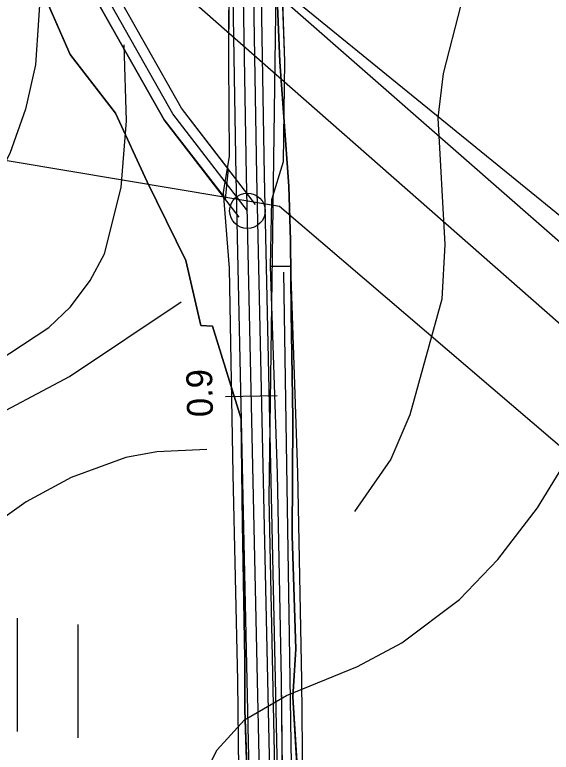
# Model space of a CAD drawing. Extents: x -662620 to -656370, y -1067090 to -1062990.
# Drawn here: x -660531.2 to -660427.3, y -1064236 to -1064093.3 of the extents above; entities that cross this region are included whole.
import ezdxf

# ---------------------------------------------------------------- set-up
doc = ezdxf.new("R2010")
doc.units = 0
for name, color, linetype in [('CESTA_ZABOR', 7, 'Continuous'), ('Default', 7, 'Continuous'), ('ELEK__VEDENÍ_VN_-_NADZEMNÍ', 7, 'Continuous'), ('ELEK__VEDENÍ_VVN_-_NADZEMNÍ', 7, 'Continuous'), ('Krajinná_zeleň_-_liniová_-_návrh', 7, 'Continuous'), ('Ochr__pás__vod__zdroje_II__stupně', 7, 'Continuous'), ('Odvodnení_cesty_príkopem_-_navržené', 7, 'Continuous'), ('ORNÁ_PŮDA_-_STÁVAJÍCÍ', 7, 'Continuous'), ('ORNÁ_PŮDA_-_ZNAČKA', 7, 'Continuous'), ('OSTATNÍ_PLOCHA_-_NAVRŽENÁ', 7, 'Continuous'), ('OSTATNÍ_PLOCHA_-_STÁVAJÍCÍ', 7, 'Continuous'), ('POLNÍ_CESTA_NAVRŽENÁ_-_OSA', 7, 'Continuous'), ('POLNÍ_CESTA_STÁVAJÍCÍ_-_KRAJ', 7, 'Continuous'), ('POLNÍ_CESTA_STÁVAJÍCÍ_-_OSA', 7, 'Continuous'), ('Trvalý_trávní_porost_-_stávající', 7, 'Continuous'), ('VRSTEVNICE_ZDŮRAZNĚNÁ', 7, 'Continuous'), ('VRSTEVNICE_ZÁKLADNÍ', 7, 'Continuous')]:
    doc.layers.add(name, color=color, linetype=linetype)

msp = doc.modelspace()

# ---------------------------------------------------------------- linework, layer by layer
at = {"layer": 'CESTA_ZABOR'}
for p, q in [((-660489.74, -1064102.3), (-660489.62, -1064062.36)), ((-660480.31, -1064062.11), (-660478.98, -1064102.23)), ((-660489.61, -1064120.63), (-660489.74, -1064102.3)), ((-660478.98, -1064102.23), (-660479.21, -1064121.73)), ((-660490.79, -1064127.68), (-660489.61, -1064120.63)), ((-660479.21, -1064121.73), (-660481.5, -1064129.07)), ((-660489.62, -1064142.29), (-660490.79, -1064127.68)), ((-660481.5, -1064129.07), (-660481.76, -1064141.99)), ((-660481.76, -1064141.99), (-660480.35, -1064182.06)), ((-660488.92, -1064182.19), (-660489.62, -1064142.29)), ((-660487.99, -1064222.18), (-660488.92, -1064182.19)), ((-660480.35, -1064182.06), (-660479.6, -1064222.07)), ((-660487.56, -1064262.16), (-660487.99, -1064222.18)), ((-660479.6, -1064222.07), (-660479.22, -1064262.06))]:
    msp.add_line(p, q, dxfattribs=at)
for points in [[(-660476.62, -1064381.82), (-660481.51, -1064342.23), (-660485.81, -1064302.25), (-660487.55, -1064267.89), (-660487.56, -1064262.16), (-660487.99, -1064222.18), (-660488.92, -1064182.19), (-660489.62, -1064142.29), (-660490.79, -1064127.68), (-660489.61, -1064120.63), (-660489.74, -1064102.3), (-660489.62, -1064062.36), (-660491.41, -1064022.4), (-660491.82, -1063995.6), (-660491.58, -1063993.71), (-660486.92, -1063981.87), (-660480, -1063962.07), (-660476.39, -1063948.94), (-660467.64, -1063925.93), (-660459.11, -1063911.53), (-660457.57, -1063907.35), (-660441.43, -1063870.67), (-660426.53, -1063833.6), (-660410.61, -1063796.9)], [(-660402.21, -1063800.45), (-660418.38, -1063837.05), (-660433.34, -1063874.17), (-660449.71, -1063910.53), (-660464.44, -1063947.85), (-660478.91, -1063984.7), (-660482.04, -1063997.01), (-660482.49, -1064022.32), (-660480.31, -1064062.11), (-660478.98, -1064102.23), (-660479.21, -1064121.73), (-660481.5, -1064129.07), (-660481.76, -1064141.99), (-660480.35, -1064182.06), (-660479.6, -1064222.07), (-660479.22, -1064262.06), (-660478.9, -1064274.43), (-660477.62, -1064301.81), (-660473.42, -1064341.28), (-660468.75, -1064381.18)], [(-660588.24, -1064193.5), (-660573.01, -1064125.57), (-660556.63, -1064051.98), (-660554.66, -1064044.43), (-660549.46, -1064039.91), (-660543.17, -1064040.28), (-660539.05, -1064046.15), (-660522.38, -1064077.97), (-660502.25, -1064113.58), (-660490.41, -1064128.91), (-660489.78, -1064123.16), (-660498.9, -1064111.37), (-660518.86, -1064076.05), (-660535.63, -1064044.06), (-660541, -1064036.4), (-660550.85, -1064035.83), (-660558.22, -1064042.22), (-660560.52, -1064051.04), (-660576.91, -1064124.7), (-660592.14, -1064192.62), (-660588.24, -1064193.5), (-660588.24, -1064193.5)], [(-660588.24, -1064193.5), (-660573.01, -1064125.57), (-660556.63, -1064051.98), (-660554.66, -1064044.43), (-660549.46, -1064039.91), (-660543.17, -1064040.28), (-660539.05, -1064046.15), (-660522.38, -1064077.97), (-660502.25, -1064113.58), (-660490.41, -1064128.91), (-660489.78, -1064123.16), (-660498.9, -1064111.37), (-660518.86, -1064076.05), (-660535.63, -1064044.06), (-660541, -1064036.4), (-660550.85, -1064035.83), (-660558.22, -1064042.22), (-660560.52, -1064051.04), (-660576.91, -1064124.7), (-660592.14, -1064192.62)]]:
    msp.add_lwpolyline(points, dxfattribs=at)
at = {"layer": 'ELEK__VEDENÍ_VN_-_NADZEMNÍ'}
msp.add_lwpolyline([(-661430.18, -1063973.15), (-661341.18, -1063987.78), (-661252.56, -1064002.41), (-661162.74, -1064017.32), (-661072.57, -1064032.36), (-660982.83, -1064047.06), (-660895.64, -1064061.52), (-660803.93, -1064076.92), (-660722.98, -1064090.23), (-660635.7, -1064104.5), (-660551.96, -1064118.27), (-660479.9, -1064130.34), (-660406.54, -1064193.02), (-660334.59, -1064253.68), (-660260.25, -1064316.77)], dxfattribs=at)
at = {"layer": 'ELEK__VEDENÍ_VVN_-_NADZEMNÍ'}
for points in [[(-659212.59, -1064402.76), (-659241.86, -1064399.78), (-659588.53, -1064364.37), (-659927.91, -1064329.98), (-660254.66, -1064303.24), (-660516.66, -1064073.17), (-660833.72, -1063804.76), (-661111.8, -1063569.65)], [(-660509.03, -1064064.22), (-660244.71, -1064279.23)], [(-659926.77, -1064317.9), (-660249.79, -1064291.25), (-660509.03, -1064064.22)], [(-660509.03, -1064064.22), (-660244.71, -1064279.23), (-659926.77, -1064317.9)], [(-660254.66, -1064303.24), (-660516.66, -1064073.17)]]:
    msp.add_lwpolyline(points, dxfattribs=at)
at = {"layer": 'Krajinná_zeleň_-_liniová_-_návrh'}
msp.add_lwpolyline([(-660463.41, -1064442), (-660476.87, -1064283.86), (-660479.09, -1064143.11)], dxfattribs=at)
at = {"layer": 'Ochr__pás__vod__zdroje_II__stupně'}
msp.add_lwpolyline([(-660464.98, -1064477.66), (-660479.16, -1064319.24), (-660481.94, -1064186.81), (-660479.3, -1063994.59), (-660360.21, -1063702.35), (-660281.08, -1063700.79), (-660243.47, -1063702.35), (-660222.31, -1063711.76), (-660211.34, -1063724.29), (-660187.06, -1063774.43), (-660164.34, -1063811.26), (-660075.02, -1063846.52), (-660042.89, -1063862.97), (-660047.59, -1063878.64), (-659927.67, -1063941.34), (-659907.68, -1063958.21), (-659897.75, -1063968.57), (-659822.34, -1063992.17), (-659732.05, -1064020.39)], dxfattribs=at)
at = {"layer": 'Odvodnení_cesty_príkopem_-_navržené'}
msp.add_lwpolyline([(-660558.09, -1065055.87), (-660475.04, -1064666.65), (-660471.14, -1064652.96), (-660465.99, -1064629.97), (-660464, -1064613.86), (-660457.68, -1064584.26), (-660456.26, -1064575.18), (-660454.42, -1064557.77), (-660456.24, -1064538.9), (-660463.06, -1064471.1), (-660479.37, -1064283.99), (-660482.8, -1064124.36), (-660484.72, -1064013.14), (-660484.26, -1063999.81), (-660482.47, -1063990.24), (-660478.65, -1063978.94), (-660368.35, -1063708.74)], dxfattribs=at)
at = {"layer": 'ORNÁ_PŮDA_-_STÁVAJÍCÍ'}
for p, q in [((-660479.89, -1064102.35), (-660481.05, -1064074.37)), ((-660478.1, -1064126.45), (-660479.89, -1064102.35)), ((-660477.81, -1064136.93), (-660478.1, -1064126.45)), ((-660477.69, -1064150.75), (-660477.81, -1064136.93)), ((-660477.33, -1064171.48), (-660477.69, -1064150.75)), ((-660477.47, -1064194.07), (-660477.33, -1064171.48)), ((-660476.74, -1064216.04), (-660477.47, -1064194.07)), ((-660477.34, -1064225.29), (-660476.74, -1064216.04)), ((-660476.34, -1064241.78), (-660477.34, -1064225.29))]:
    msp.add_line(p, q, dxfattribs=at)
msp.add_lwpolyline([(-660470.29, -1064374.22), (-660471.09, -1064362.63), (-660471.94, -1064349.57), (-660473.08, -1064336.89), (-660473.74, -1064320.03), (-660474.29, -1064302.76), (-660474.79, -1064291.24), (-660476.03, -1064274.2), (-660476.13, -1064259.82), (-660476.34, -1064241.78), (-660477.34, -1064225.29), (-660476.74, -1064216.04), (-660477.47, -1064194.07), (-660477.33, -1064171.48), (-660477.69, -1064150.75), (-660477.81, -1064136.93), (-660478.1, -1064126.45), (-660479.89, -1064102.35), (-660481.05, -1064074.37)], dxfattribs=at)
at = {"layer": 'ORNÁ_PŮDA_-_ZNAČKA'}
for points in [[(-660530.7, -1064210.08), (-660530.7, -1064232.01)], [(-660519, -1064211.31), (-660519, -1064233.24)]]:
    msp.add_lwpolyline(points, dxfattribs=at)
at = {"layer": 'OSTATNÍ_PLOCHA_-_NAVRŽENÁ'}
msp.add_lwpolyline([(-660481.76, -1064141.99), (-660480.35, -1064182.06), (-660479.6, -1064222.07), (-660479.22, -1064262.06), (-660478.9, -1064274.43), (-660477.62, -1064301.81), (-660473.42, -1064341.28), (-660468.75, -1064381.18), (-660465.77, -1064421.09), (-660463.02, -1064443.82), (-660461.97, -1064448.3), (-660459.31, -1064450.58), (-660461.78, -1064420.77), (-660464.77, -1064380.8), (-660469.45, -1064340.83), (-660473.63, -1064301.5), (-660474.9, -1064274.29), (-660475.22, -1064261.99), (-660475.6, -1064222.01), (-660476.35, -1064181.95), (-660477.76, -1064141.96)], close=True, dxfattribs=at)
msp.add_lwpolyline([(-660481.76, -1064141.99), (-660480.35, -1064182.06), (-660479.6, -1064222.07), (-660479.22, -1064262.06), (-660478.9, -1064274.43), (-660477.62, -1064301.81), (-660473.42, -1064341.28), (-660468.75, -1064381.18), (-660465.77, -1064421.09), (-660463.02, -1064443.82), (-660461.97, -1064448.3), (-660459.31, -1064450.58), (-660461.78, -1064420.77), (-660464.77, -1064380.8), (-660469.45, -1064340.83), (-660473.63, -1064301.5), (-660474.9, -1064274.29), (-660475.22, -1064261.99), (-660475.6, -1064222.01), (-660476.35, -1064181.95), (-660477.76, -1064141.96)], close=True, dxfattribs=at)
at = {"layer": 'OSTATNÍ_PLOCHA_-_STÁVAJÍCÍ'}
for p, q in [((-660481.05, -1064074.37), (-660479.89, -1064102.35)), ((-660481.05, -1064074.37), (-660479.89, -1064102.35)), ((-660520.43, -1064100.97), (-660529.29, -1064080.76)), ((-660520.43, -1064100.97), (-660529.29, -1064080.76)), ((-660511.66, -1064112.29), (-660520.43, -1064100.97)), ((-660511.66, -1064112.29), (-660520.43, -1064100.97)), ((-660479.89, -1064102.35), (-660478.1, -1064126.45)), ((-660479.89, -1064102.35), (-660478.1, -1064126.45)), ((-660505.56, -1064125.57), (-660511.66, -1064112.29)), ((-660505.56, -1064125.57), (-660511.66, -1064112.29)), ((-660498.07, -1064140.85), (-660505.56, -1064125.57)), ((-660498.07, -1064140.85), (-660505.56, -1064125.57)), ((-660478.1, -1064126.45), (-660477.81, -1064136.93)), ((-660478.1, -1064126.45), (-660477.81, -1064136.93)), ((-660477.81, -1064136.93), (-660477.69, -1064150.75)), ((-660477.81, -1064136.93), (-660477.69, -1064150.75)), ((-660495.19, -1064153.41), (-660498.07, -1064140.85)), ((-660495.19, -1064153.41), (-660498.07, -1064140.85)), ((-660477.69, -1064150.75), (-660477.33, -1064171.48)), ((-660477.69, -1064150.75), (-660477.33, -1064171.48)), ((-660492.89, -1064153.57), (-660495.19, -1064153.41)), ((-660492.89, -1064153.57), (-660495.19, -1064153.41)), ((-660487.32, -1064171.49), (-660492.89, -1064153.57)), ((-660487.32, -1064171.49), (-660492.89, -1064153.57)), ((-660487.12, -1064191.78), (-660487.32, -1064171.49)), ((-660487.12, -1064191.78), (-660487.32, -1064171.49)), ((-660477.33, -1064171.48), (-660477.47, -1064194.07)), ((-660477.33, -1064171.48), (-660477.47, -1064194.07)), ((-660486.64, -1064217.91), (-660487.12, -1064191.78)), ((-660486.64, -1064217.91), (-660487.12, -1064191.78)), ((-660477.47, -1064194.07), (-660476.74, -1064216.04)), ((-660477.47, -1064194.07), (-660476.74, -1064216.04)), ((-660476.74, -1064216.04), (-660477.34, -1064225.29)), ((-660476.74, -1064216.04), (-660477.34, -1064225.29)), ((-660486.67, -1064227.81), (-660486.64, -1064217.91)), ((-660486.67, -1064227.81), (-660486.64, -1064217.91)), ((-660477.34, -1064225.29), (-660476.34, -1064241.78)), ((-660477.34, -1064225.29), (-660476.34, -1064241.78)), ((-660486.09, -1064244.12), (-660486.67, -1064227.81)), ((-660486.09, -1064244.12), (-660486.67, -1064227.81))]:
    msp.add_line(p, q, dxfattribs=at)
for points in [[(-660479.03, -1064374.35), (-660481.22, -1064361.46), (-660482.83, -1064343.31), (-660485.34, -1064319.01), (-660524.58, -1064322.57), (-660499.48, -1064320.24), (-660485.42, -1064318.9), (-660485.23, -1064289.19), (-660485.99, -1064273.97), (-660486.31, -1064260.54), (-660486.09, -1064244.12), (-660486.67, -1064227.81), (-660486.64, -1064217.91), (-660487.12, -1064191.78), (-660487.32, -1064171.49), (-660492.89, -1064153.57), (-660495.19, -1064153.41), (-660498.07, -1064140.85), (-660505.56, -1064125.57), (-660511.66, -1064112.29), (-660520.43, -1064100.97), (-660529.29, -1064080.76), (-660534.95, -1064065.62)], [(-660479.03, -1064374.35), (-660481.22, -1064361.46), (-660482.83, -1064343.31), (-660485.34, -1064319.01), (-660524.58, -1064322.57), (-660499.48, -1064320.24), (-660485.42, -1064318.9), (-660485.23, -1064289.19), (-660485.99, -1064273.97), (-660486.31, -1064260.54), (-660486.09, -1064244.12), (-660486.67, -1064227.81), (-660486.64, -1064217.91), (-660487.12, -1064191.78), (-660487.32, -1064171.49), (-660492.89, -1064153.57), (-660495.19, -1064153.41), (-660498.07, -1064140.85), (-660505.56, -1064125.57), (-660511.66, -1064112.29), (-660520.43, -1064100.97), (-660529.29, -1064080.76), (-660534.95, -1064065.62)], [(-660481.05, -1064074.37), (-660479.89, -1064102.35), (-660478.1, -1064126.45), (-660477.81, -1064136.93), (-660477.69, -1064150.75), (-660477.33, -1064171.48), (-660477.47, -1064194.07), (-660476.74, -1064216.04), (-660477.34, -1064225.29), (-660476.34, -1064241.78), (-660476.13, -1064259.82), (-660476.03, -1064274.2), (-660474.79, -1064291.24), (-660474.29, -1064302.76), (-660473.74, -1064320.03), (-660473.08, -1064336.89), (-660471.94, -1064349.57), (-660471.09, -1064362.63), (-660470.29, -1064374.22)], [(-660481.05, -1064074.37), (-660479.89, -1064102.35), (-660478.1, -1064126.45), (-660477.81, -1064136.93), (-660477.69, -1064150.75), (-660477.33, -1064171.48), (-660477.47, -1064194.07), (-660476.74, -1064216.04), (-660477.34, -1064225.29), (-660476.34, -1064241.78), (-660476.13, -1064259.82), (-660476.03, -1064274.2), (-660474.79, -1064291.24), (-660474.29, -1064302.76), (-660473.74, -1064320.03), (-660473.08, -1064336.89), (-660471.94, -1064349.57), (-660471.09, -1064362.63), (-660470.29, -1064374.22)]]:
    msp.add_lwpolyline(points, dxfattribs=at)
at = {"layer": 'POLNÍ_CESTA_NAVRŽENÁ_-_OSA'}
for points in [[(-660561.51, -1065055.14), (-660462.91, -1064592.2), (-660459.73, -1064574.68), (-660457.94, -1064557.76), (-660459.73, -1064539.24), (-660466.54, -1064471.42), (-660482.86, -1064284.18), (-660486.3, -1064124.42), (-660488.22, -1064013.11), (-660487.75, -1063999.42), (-660485.86, -1063989.36), (-660481.93, -1063977.72), (-660371.59, -1063707.42)], [(-660490.38, -1064167.18), (-660480.38, -1064166.97)]]:
    msp.add_lwpolyline(points, dxfattribs=at)
at = {"layer": 'POLNÍ_CESTA_STÁVAJÍCÍ_-_KRAJ'}
for points in [[(-660563.47, -1065054.73), (-660464.88, -1064591.81), (-660461.71, -1064574.4), (-660459.95, -1064557.75), (-660461.72, -1064539.44), (-660468.53, -1064471.61), (-660484.86, -1064284.29), (-660488.3, -1064124.46), (-660490.22, -1064013.09), (-660489.75, -1063999.2), (-660487.8, -1063988.85), (-660483.81, -1063977.02), (-660477.71, -1063961.92), (-660474.07, -1063948.91), (-660465.37, -1063926.71), (-660457.21, -1063913), (-660373.44, -1063706.66)], [(-660559.56, -1065055.56), (-660475.57, -1064663), (-660472.75, -1064654.02), (-660466.98, -1064628.93), (-660465.02, -1064612.2), (-660460.95, -1064592.59), (-660457.75, -1064574.96), (-660455.93, -1064557.77), (-660457.74, -1064539.05), (-660464.55, -1064471.24), (-660480.86, -1064284.07), (-660484.3, -1064124.39), (-660486.22, -1064013.13), (-660485.76, -1063999.64), (-660483.92, -1063989.86), (-660480.06, -1063978.41), (-660369.74, -1063708.17)], [(-660484.57, -1064129.99), (-660498.9, -1064111.37), (-660518.86, -1064076.05), (-660535.63, -1064044.06), (-660541, -1064036.4), (-660550.85, -1064035.83), (-660558.22, -1064042.22), (-660560.52, -1064051.04), (-660576.91, -1064124.7), (-660592.14, -1064192.62)], [(-660487.74, -1064132.43), (-660502.25, -1064113.58), (-660522.38, -1064077.97), (-660539.05, -1064046.15), (-660543.17, -1064040.28), (-660549.46, -1064039.91), (-660554.66, -1064044.43), (-660556.63, -1064051.98), (-660573.01, -1064125.57), (-660588.24, -1064193.5)]]:
    msp.add_lwpolyline(points, dxfattribs=at)
msp.add_circle((-660486.15, -1064131.21), 3.43, dxfattribs=at)
at = {"layer": 'POLNÍ_CESTA_STÁVAJÍCÍ_-_OSA'}
msp.add_lwpolyline([(-660486.15, -1064131.21), (-660500.57, -1064112.47), (-660520.62, -1064077.01), (-660537.34, -1064045.1), (-660542.09, -1064038.34), (-660550.15, -1064037.87), (-660556.44, -1064043.33), (-660558.57, -1064051.51), (-660574.96, -1064125.14), (-660590.19, -1064193.06)], dxfattribs=at)
at = {"layer": 'Trvalý_trávní_porost_-_stávající'}
for p, q in [((-660529.29, -1064080.76), (-660520.43, -1064100.97)), ((-660520.43, -1064100.97), (-660511.66, -1064112.29)), ((-660511.66, -1064112.29), (-660505.56, -1064125.57)), ((-660505.56, -1064125.57), (-660498.07, -1064140.85)), ((-660498.07, -1064140.85), (-660495.19, -1064153.41)), ((-660495.19, -1064153.41), (-660492.89, -1064153.57)), ((-660492.89, -1064153.57), (-660487.32, -1064171.49)), ((-660487.32, -1064171.49), (-660487.12, -1064191.78)), ((-660487.12, -1064191.78), (-660486.64, -1064217.91)), ((-660486.64, -1064217.91), (-660486.67, -1064227.81)), ((-660486.67, -1064227.81), (-660486.09, -1064244.12))]:
    msp.add_line(p, q, dxfattribs=at)
msp.add_lwpolyline([(-660534.95, -1064065.62), (-660529.29, -1064080.76), (-660520.43, -1064100.97), (-660511.66, -1064112.29), (-660505.56, -1064125.57), (-660498.07, -1064140.85), (-660495.19, -1064153.41), (-660492.89, -1064153.57), (-660487.32, -1064171.49), (-660487.12, -1064191.78), (-660486.64, -1064217.91), (-660486.67, -1064227.81), (-660486.09, -1064244.12), (-660486.31, -1064260.54), (-660485.99, -1064273.97), (-660485.23, -1064289.19), (-660485.42, -1064318.9), (-660499.48, -1064320.24), (-660524.58, -1064322.57), (-660522.09, -1064347.37), (-660502.38, -1064345.51), (-660482.83, -1064343.31), (-660481.22, -1064361.46), (-660479.03, -1064374.35)], dxfattribs=at)
at = {"layer": 'VRSTEVNICE_ZDŮRAZNĚNÁ'}
msp.add_lwpolyline([(-660570.87, -1064374.23), (-660570.87, -1064346.21), (-660570.3, -1064342.21), (-660566.44, -1064330.21), (-660557.87, -1064314.2), (-660556.29, -1064310.19), (-660554.58, -1064302.48), (-660553.86, -1064295.04), (-660554.29, -1064280.18), (-660555.58, -1064269.03), (-660559.72, -1064250.45), (-660566.01, -1064228.15), (-660568.16, -1064213.29), (-660566.87, -1064205.85), (-660563.73, -1064198.42), (-660559.58, -1064190.99), (-660554.29, -1064184.56), (-660538.14, -1064172.55), (-660520.56, -1064163.26), (-660498.98, -1064148.82)], dxfattribs=at)
at = {"layer": 'VRSTEVNICE_ZÁKLADNÍ'}
for points in [[(-660428.97, -1063922.24), (-660435.23, -1063928.42), (-660440.8, -1063935.14), (-660449.67, -1063948.15), (-660453.83, -1063955.76), (-660457.19, -1063964.31), (-660457.98, -1063969.51), (-660456.53, -1063987.74), (-660452.53, -1064005.75), (-660441.74, -1064028.12), (-660438.66, -1064038.34), (-660436.23, -1064050.34), (-660436.23, -1064065.92), (-660437.82, -1064075.21), (-660444.81, -1064091.37), (-660448.24, -1064104.66), (-660449.24, -1064113.23), (-660447.93, -1064137.75), (-660448.52, -1064148.34), (-660454.67, -1064170.69), (-660458.39, -1064179.27), (-660465.39, -1064189.42)], [(-660522.91, -1064070.93), (-660525.42, -1064076.93), (-660527.14, -1064102.94), (-660529.14, -1064111.52), (-660532.14, -1064120.09), (-660535.71, -1064126.96), (-660554.86, -1064151.97), (-660563.58, -1064164.55), (-660571.3, -1064179.55), (-660574.73, -1064188.13), (-660578.3, -1064201.85), (-660581.02, -1064217.29), (-660582.02, -1064234.44), (-660580.74, -1064254.17), (-660576.59, -1064284.18), (-660576.16, -1064294.19), (-660578.02, -1064306.19), (-660582.88, -1064324.2), (-660586.17, -1064340.21), (-660587.17, -1064350.22), (-660587.6, -1064380.52)], [(-660522.91, -1064070.93), (-660525.42, -1064076.93), (-660527.14, -1064102.94), (-660529.14, -1064111.52), (-660532.14, -1064120.09), (-660535.71, -1064126.96), (-660554.86, -1064151.97), (-660563.58, -1064164.55), (-660571.3, -1064179.55), (-660574.73, -1064188.13), (-660578.3, -1064201.85), (-660581.02, -1064217.29), (-660582.02, -1064234.44), (-660580.74, -1064254.17), (-660576.59, -1064284.18), (-660576.16, -1064294.19), (-660578.02, -1064306.19), (-660582.88, -1064324.2), (-660586.17, -1064340.21), (-660587.17, -1064350.22), (-660587.6, -1064380.52)], [(-660582.16, -1064385.66), (-660574.59, -1064319.91), (-660571.59, -1064303.05), (-660570.3, -1064287.61), (-660570.59, -1064274.75), (-660574.59, -1064254.17), (-660575.59, -1064243.87), (-660575.59, -1064223.29), (-660575.02, -1064215.57), (-660572.87, -1064202.71), (-660570.44, -1064194.99), (-660567.73, -1064189.85), (-660559.87, -1064179.55), (-660554.58, -1064174.41), (-660547.29, -1064168.69), (-660524.56, -1064153.83), (-660520.42, -1064149.82), (-660516.56, -1064144.68), (-660513.84, -1064139.53), (-660510.56, -1064126.67), (-660509.55, -1064113.81), (-660509.98, -1064099.08)], [(-660582.16, -1064385.66), (-660574.59, -1064319.91), (-660571.59, -1064303.05), (-660570.3, -1064287.61), (-660570.59, -1064274.75), (-660574.59, -1064254.17), (-660575.59, -1064243.87), (-660575.59, -1064223.29), (-660575.02, -1064215.57), (-660572.87, -1064202.71), (-660570.44, -1064194.99), (-660567.73, -1064189.85), (-660559.87, -1064179.55), (-660554.58, -1064174.41), (-660547.29, -1064168.69), (-660524.56, -1064153.83), (-660520.42, -1064149.82), (-660516.56, -1064144.68), (-660513.84, -1064139.53), (-660510.56, -1064126.67), (-660509.55, -1064113.81), (-660509.98, -1064099.08)], [(-660495.12, -1064241.59), (-660491.97, -1064235.58), (-660486.69, -1064229.72), (-660478.54, -1064225.01), (-660464.82, -1064219.43), (-660456.24, -1064214.86), (-660445.09, -1064206.43), (-660437.66, -1064198.71), (-660429.94, -1064188.7), (-660425.08, -1064180.7), (-660418.65, -1064166.69), (-660412.36, -1064150.68), (-660406.5, -1064138.68), (-660401.64, -1064132.82), (-660394.69, -1064128.53), (-660390.53, -1064127.79), (-660383.63, -1064128.1), (-660376.63, -1064130.96), (-660372.2, -1064133.67), (-660363.48, -1064140.96)], [(-660495.12, -1064241.59), (-660491.97, -1064235.58), (-660486.69, -1064229.72), (-660478.54, -1064225.01), (-660464.82, -1064219.43), (-660456.24, -1064214.86), (-660445.09, -1064206.43), (-660437.66, -1064198.71), (-660429.94, -1064188.7), (-660425.08, -1064180.7), (-660418.65, -1064166.69), (-660412.36, -1064150.68), (-660406.5, -1064138.68), (-660401.64, -1064132.82), (-660394.69, -1064128.53), (-660390.53, -1064127.79), (-660383.63, -1064128.1), (-660376.63, -1064130.96), (-660372.2, -1064133.67), (-660363.48, -1064140.96)], [(-660493.97, -1064177.39), (-660503.7, -1064177.84), (-660509.7, -1064178.98), (-660520.28, -1064182.84), (-660528.99, -1064187.56), (-660536.28, -1064192.7), (-660541.72, -1064198.14), (-660545.43, -1064203.57), (-660548.72, -1064211.86), (-660549.15, -1064214.72), (-660548.43, -1064223.01), (-660540, -1064250.45), (-660536.43, -1064265.89), (-660534.85, -1064277.89), (-660534.85, -1064289.61), (-660536.86, -1064301.62), (-660540.14, -1064311.91), (-660548.86, -1064329.78), (-660551.43, -1064337.64), (-660552.15, -1064351.36), (-660549.58, -1064371.94)], [(-660493.97, -1064177.39), (-660503.7, -1064177.84), (-660509.7, -1064178.98), (-660520.28, -1064182.84), (-660528.99, -1064187.56), (-660536.28, -1064192.7), (-660541.72, -1064198.14), (-660545.43, -1064203.57), (-660548.72, -1064211.86), (-660549.15, -1064214.72), (-660548.43, -1064223.01), (-660540, -1064250.45), (-660536.43, -1064265.89), (-660534.85, -1064277.89), (-660534.85, -1064289.61), (-660536.86, -1064301.62), (-660540.14, -1064311.91), (-660548.86, -1064329.78), (-660551.43, -1064337.64), (-660552.15, -1064351.36), (-660549.58, -1064371.94)]]:
    msp.add_lwpolyline(points, dxfattribs=at)

# ---------------------------------------------------------------- texts
at = {"layer": 'Default'}
msp.add_text('0.9', height=5, rotation=91.232, dxfattribs=at).set_placement((-660492.8, -1064171.09))

doc.saveas('drawing.dxf')
